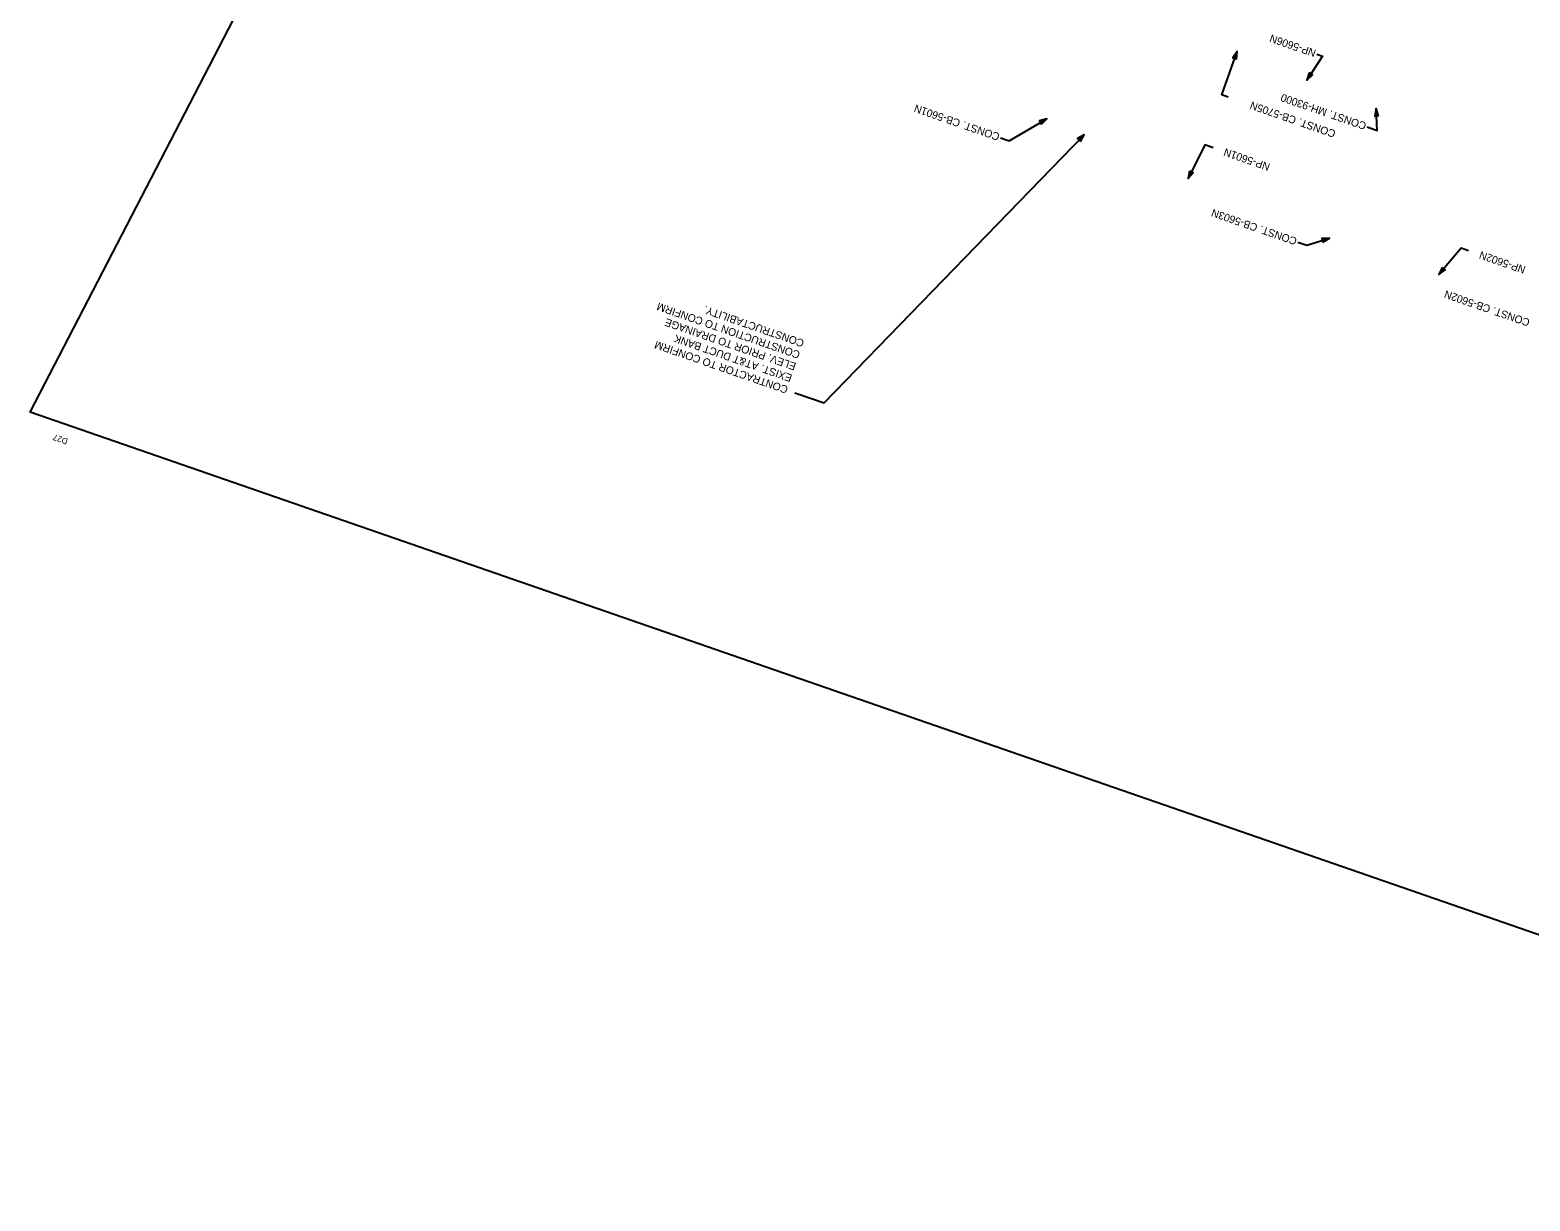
# Model space of a CAD drawing. Extents: x 1607775 to 1609652, y 1093977 to 1095566.
# Drawn here: x 1607775 to 1608751, y 1093977 to 1094739 of the extents above; entities that cross this region are included whole.
import ezdxf

# ---------------------------------------------------------------- set-up
doc = ezdxf.new("R2010")
doc.units = 0
for name, color, linetype in [('RD_PD_DR_ErosCtrl', 7, 'Continuous'), ('RD_PD_Final_Cl', 7, 'Continuous'), ('RD_PD_MedBWall', 7, 'Continuous')]:
    doc.layers.add(name, color=color, linetype=linetype)

msp = doc.modelspace()

# ---------------------------------------------------------------- linework, layer by layer
at = {"layer": 'RD_PD_DR_ErosCtrl'}
msp.add_lwpolyline([(1609319.26, 1094082.92), (1609257.16, 1093976.84), (1607774.66, 1094490.39), (1607913.49, 1094758.18), (1608083.85, 1095087.22), (1608184.77, 1095282.94), (1608412.15, 1095241.23), (1608411.67, 1095239.7), (1609329.12, 1094923.25), (1609333.64, 1094914.63), (1609347.07, 1094917.06), (1609439, 1094885.35), (1609428.8, 1094854.27), (1609615.32, 1094789.49), (1609546.66, 1094678.85), (1609459.72, 1094656.09), (1609449.74, 1094513.93), (1609414.43, 1094518.3), (1609397.89, 1094407.56), (1609403.67, 1094397.48), (1609379.74, 1094297.75), (1609387.82, 1094283.49), (1609353.45, 1094193.74), (1609389.72, 1094179.44)], close=True, dxfattribs=at)
msp.add_lwpolyline([(1609319.26, 1094082.92), (1609257.16, 1093976.84), (1607774.66, 1094490.39), (1607913.49, 1094758.18), (1608083.85, 1095087.22), (1608184.77, 1095282.94), (1608412.15, 1095241.23), (1608411.67, 1095239.7), (1609329.12, 1094923.25), (1609333.64, 1094914.63), (1609347.07, 1094917.06), (1609439, 1094885.35), (1609428.8, 1094854.27), (1609615.32, 1094789.49), (1609546.66, 1094678.85), (1609459.72, 1094656.09), (1609449.74, 1094513.93), (1609414.43, 1094518.3), (1609397.89, 1094407.56), (1609403.67, 1094397.48), (1609379.74, 1094297.75), (1609387.82, 1094283.49), (1609353.45, 1094193.74), (1609389.72, 1094179.44)], close=True, dxfattribs=at)
msp.add_lwpolyline([(1609319.26, 1094082.92), (1609257.16, 1093976.84), (1607774.66, 1094490.39), (1607913.49, 1094758.18), (1608083.85, 1095087.22), (1608184.77, 1095282.94), (1608412.15, 1095241.23), (1608411.67, 1095239.7), (1609329.12, 1094923.25), (1609333.64, 1094914.63), (1609347.07, 1094917.06), (1609439, 1094885.35), (1609428.8, 1094854.27), (1609615.32, 1094789.49), (1609546.66, 1094678.85), (1609459.72, 1094656.09), (1609449.74, 1094513.93), (1609414.43, 1094518.3), (1609397.89, 1094407.56), (1609403.67, 1094397.48), (1609379.74, 1094297.75), (1609387.82, 1094283.49), (1609353.45, 1094193.74), (1609389.72, 1094179.44)], close=True, dxfattribs=at)
msp.add_lwpolyline([(1609319.26, 1094082.92), (1609257.16, 1093976.84), (1607774.66, 1094490.39), (1607913.49, 1094758.18), (1608083.85, 1095087.22), (1608184.77, 1095282.94), (1608412.15, 1095241.23), (1608411.67, 1095239.7), (1609329.12, 1094923.25), (1609333.64, 1094914.63), (1609347.07, 1094917.06), (1609439, 1094885.35), (1609428.8, 1094854.27), (1609615.32, 1094789.49), (1609546.66, 1094678.85), (1609459.72, 1094656.09), (1609449.74, 1094513.93), (1609414.43, 1094518.3), (1609397.89, 1094407.56), (1609403.67, 1094397.48), (1609379.74, 1094297.75), (1609387.82, 1094283.49), (1609353.45, 1094193.74), (1609389.72, 1094179.44)], close=True, dxfattribs=at)
msp.add_lwpolyline([(1609319.26, 1094082.92), (1609257.16, 1093976.84), (1607774.66, 1094490.39), (1607913.49, 1094758.18), (1608083.85, 1095087.22), (1608184.77, 1095282.94), (1608412.15, 1095241.23), (1608411.67, 1095239.7), (1609329.12, 1094923.25), (1609333.64, 1094914.63), (1609347.07, 1094917.06), (1609439, 1094885.35), (1609428.8, 1094854.27), (1609615.32, 1094789.49), (1609546.66, 1094678.85), (1609459.72, 1094656.09), (1609449.74, 1094513.93), (1609414.43, 1094518.3), (1609397.89, 1094407.56), (1609403.67, 1094397.48), (1609379.74, 1094297.75), (1609387.82, 1094283.49), (1609353.45, 1094193.74), (1609389.72, 1094179.44)], close=True, dxfattribs=at)
msp.add_lwpolyline([(1609319.26, 1094082.92), (1609257.16, 1093976.84), (1607774.66, 1094490.39), (1607913.49, 1094758.18), (1608083.85, 1095087.22), (1608184.77, 1095282.94), (1608412.15, 1095241.23), (1608411.67, 1095239.7), (1609329.12, 1094923.25), (1609333.64, 1094914.63), (1609347.07, 1094917.06), (1609439, 1094885.35), (1609428.8, 1094854.27), (1609615.32, 1094789.49), (1609546.66, 1094678.85), (1609459.72, 1094656.09), (1609449.74, 1094513.93), (1609414.43, 1094518.3), (1609397.89, 1094407.56), (1609403.67, 1094397.48), (1609379.74, 1094297.75), (1609387.82, 1094283.49), (1609353.45, 1094193.74), (1609389.72, 1094179.44)], close=True, dxfattribs=at)
at = {"layer": 'RD_PD_MedBWall'}
for points in [[(1608554.96, 1094695.35), (1608550.67, 1094696.84), (1608560.68, 1094725.21)], [(1608612.6, 1094723.46), (1608616.22, 1094722.21), (1608606.09, 1094706.53)], [(1608645.46, 1094676.01), (1608652, 1094673.75), (1608651.36, 1094687.96)], [(1608406.7, 1094668.97), (1608412.26, 1094667.05), (1608436.81, 1094681.29)], [(1608272.65, 1094503.02), (1608291.78, 1094496.4), (1608461.17, 1094670.97)], [(1608545.03, 1094662.43), (1608539.66, 1094664.29), (1608528.81, 1094642.41)], [(1608600.29, 1094601), (1608606.06, 1094599), (1608620.85, 1094603.63)], [(1608711.43, 1094595.45), (1608706.57, 1094597.13), (1608692.06, 1094580.08)]]:
    msp.add_lwpolyline(points, dxfattribs=at)
for points in [[(1608560.3, 1094720.22), (1608560.68, 1094725.21), (1608557.86, 1094721.08)], [(1608607.63, 1094711.29), (1608606.09, 1094706.53), (1608609.8, 1094709.89)], [(1608652.87, 1094683.2), (1608651.36, 1094687.96), (1608650.29, 1094683.08)], [(1608433.28, 1094677.75), (1608436.81, 1094681.29), (1608431.98, 1094679.99)], [(1608458.73, 1094666.61), (1608461.17, 1094670.97), (1608456.87, 1094668.41)], [(1608529.79, 1094647.31), (1608528.81, 1094642.41), (1608532.11, 1094646.16)], [(1608616.63, 1094600.95), (1608620.85, 1094603.63), (1608615.85, 1094603.42)], [(1608694.21, 1094584.59), (1608692.06, 1094580.08), (1608696.18, 1094582.92)]]:
    msp.add_lwpolyline(points, close=True, dxfattribs=at)

# ---------------------------------------------------------------- texts
at = {"layer": 'RD_PD_Final_Cl'}
msp.add_text('D27', height=4, rotation=160.90131, dxfattribs=at).set_placement((1607799.72, 1094472.96))
at = {"layer": 'RD_PD_MedBWall'}
for s, p in [('NP-5606N', (1608612.48, 1094726.15)), ('CONST. MH-93000', (1608645.34, 1094678.7)), ('CONST. CB-5601N', (1608406.58, 1094671.66)), ('CONST. CB-5705N', (1608625.33, 1094673.63)), ('NP-5601N', (1608582.58, 1094652.07)), ('CONST. CB-5603N', (1608600.16, 1094603.69)), ('NP-5602N', (1608748.99, 1094585.09)), ('CONSTRUCTION TO CONFIRM', (1608276.6, 1094529.7)), ('CONST. CB-5602N', (1608751.82, 1094550.7)), ('ELEV. PRIOR TO DRAINAGE', (1608273.98, 1094522.14)), ('CONSTRUCTABILITY.', (1608279.22, 1094537.26)), ('CONTRACTOR TO CONFIRM', (1608268.75, 1094507.02)), ('EXIST. AT&T DUCT BANK', (1608271.36, 1094514.58))]:
    msp.add_text(s, height=5, rotation=160.90131, dxfattribs=at).set_placement(p)

doc.saveas('drawing.dxf')
